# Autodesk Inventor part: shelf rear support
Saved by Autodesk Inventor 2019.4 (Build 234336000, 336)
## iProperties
Created: 2020-09
Part Number: shelf rear support
Material: Generic
Document SubType Name: Modeling
Designer: Administrator
Density: 1 g/cm^3
Appearance: Default
Title: shelf rear support
Author: Administrator
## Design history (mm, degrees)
feature "Body1"
body "Solid1"
